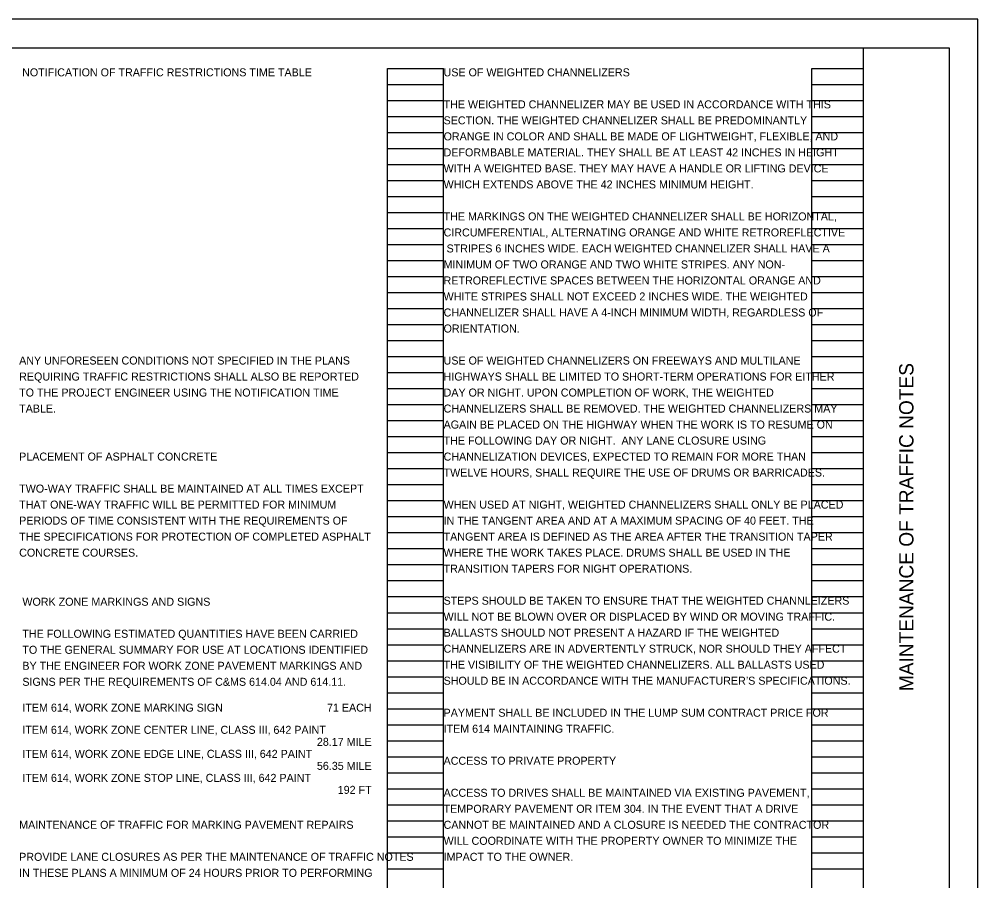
# Model space of a CAD drawing. Extents: x 0 to 34, y -8.1 to 22.
# Drawn here: x 17.24 to 34, y 6.93 to 22 of the extents above; entities that cross this region are included whole.
import ezdxf

# ---------------------------------------------------------------- set-up
doc = ezdxf.new("R2010")
doc.units = 0
for name, color, linetype in [('SH_Border', 7, 'Continuous'), ('SH_Cut_Line', 7, 'Continuous'), ('SH_Data', 7, 'Continuous'), ('SH_Text', 7, 'Continuous')]:
    doc.layers.add(name, color=color, linetype=linetype)

msp = doc.modelspace()

# ---------------------------------------------------------------- linework, layer by layer
at = {"layer": 'SH_Border'}
msp.add_line((32, 0.5), (32, 21.5), dxfattribs=at)
msp.add_lwpolyline([(1.5, 21.5), (33.5, 21.5), (33.5, 0.5), (1.5, 0.5)], close=True, dxfattribs=at)
at = {"layer": 'SH_Cut_Line'}
msp.add_lwpolyline([(0, 0), (34, 0), (34, 22), (0, 22)], close=True, dxfattribs=at)
at = {"layer": 'SH_Data'}
for p, q in [((23.68, 0.98), (23.68, 21.14)), ((23.68, 21.14), (24.66, 21.14)), ((24.66, 0.98), (24.66, 21.14)), ((31.1, 0.98), (31.1, 21.14)), ((31.1, 21.14), (32, 21.14)), ((32, 0.98), (32, 21.14)), ((23.68, 20.86), (24.66, 20.86)), ((31.1, 20.86), (32, 20.86)), ((23.68, 20.58), (24.66, 20.58)), ((31.1, 20.58), (32, 20.58)), ((23.68, 20.3), (24.66, 20.3)), ((31.1, 20.3), (32, 20.3)), ((23.68, 20.02), (24.66, 20.02)), ((31.1, 20.02), (32, 20.02)), ((23.68, 19.74), (24.66, 19.74)), ((31.1, 19.74), (32, 19.74)), ((23.68, 19.46), (24.66, 19.46)), ((31.1, 19.46), (32, 19.46)), ((23.68, 19.18), (24.66, 19.18)), ((31.1, 19.18), (32, 19.18)), ((23.68, 18.9), (24.66, 18.9)), ((31.1, 18.9), (32, 18.9)), ((23.68, 18.62), (24.66, 18.62)), ((31.1, 18.62), (32, 18.62)), ((23.68, 18.34), (24.66, 18.34)), ((31.1, 18.34), (32, 18.34)), ((23.68, 18.06), (24.66, 18.06)), ((31.1, 18.06), (32, 18.06)), ((23.68, 17.78), (24.66, 17.78)), ((31.1, 17.78), (32, 17.78)), ((23.68, 17.5), (24.66, 17.5)), ((31.1, 17.5), (32, 17.5)), ((23.68, 17.22), (24.66, 17.22)), ((31.1, 17.22), (32, 17.22)), ((23.68, 16.94), (24.66, 16.94)), ((31.1, 16.94), (32, 16.94)), ((23.68, 16.66), (24.66, 16.66)), ((31.1, 16.66), (32, 16.66)), ((23.68, 16.38), (24.66, 16.38)), ((31.1, 16.38), (32, 16.38)), ((23.68, 16.1), (24.66, 16.1)), ((31.1, 16.1), (32, 16.1)), ((23.68, 15.82), (24.66, 15.82)), ((31.1, 15.82), (32, 15.82)), ((23.68, 15.54), (24.66, 15.54)), ((31.1, 15.54), (32, 15.54)), ((23.68, 15.26), (24.66, 15.26)), ((31.1, 15.26), (32, 15.26)), ((23.68, 14.98), (24.66, 14.98)), ((31.1, 14.98), (32, 14.98)), ((23.68, 14.7), (24.66, 14.7)), ((31.1, 14.7), (32, 14.7)), ((23.68, 14.42), (24.66, 14.42)), ((31.1, 14.42), (32, 14.42)), ((23.68, 14.14), (24.66, 14.14)), ((31.1, 14.14), (32, 14.14)), ((23.68, 13.86), (24.66, 13.86)), ((31.1, 13.86), (32, 13.86)), ((23.68, 13.58), (24.66, 13.58)), ((31.1, 13.58), (32, 13.58)), ((23.68, 13.3), (24.66, 13.3)), ((31.1, 13.3), (32, 13.3)), ((23.68, 13.02), (24.66, 13.02)), ((31.1, 13.02), (32, 13.02)), ((23.68, 12.74), (24.66, 12.74)), ((31.1, 12.74), (32, 12.74)), ((23.68, 12.46), (24.66, 12.46)), ((31.1, 12.46), (32, 12.46)), ((23.68, 12.18), (24.66, 12.18)), ((31.1, 12.18), (32, 12.18)), ((23.68, 11.9), (24.66, 11.9)), ((31.1, 11.9), (32, 11.9)), ((23.68, 11.62), (24.66, 11.62)), ((31.1, 11.62), (32, 11.62)), ((23.68, 11.34), (24.66, 11.34)), ((31.1, 11.34), (32, 11.34)), ((23.68, 11.06), (24.66, 11.06)), ((31.1, 11.06), (32, 11.06)), ((23.68, 10.78), (24.66, 10.78)), ((31.1, 10.78), (32, 10.78)), ((23.68, 10.5), (24.66, 10.5)), ((31.1, 10.5), (32, 10.5)), ((23.68, 10.22), (24.66, 10.22)), ((31.1, 10.22), (32, 10.22)), ((23.68, 9.94), (24.66, 9.94)), ((31.1, 9.94), (32, 9.94)), ((23.68, 9.66), (24.66, 9.66)), ((31.1, 9.66), (32, 9.66)), ((23.68, 9.38), (24.66, 9.38)), ((31.1, 9.38), (32, 9.38)), ((23.68, 9.1), (24.66, 9.1)), ((31.1, 9.1), (32, 9.1)), ((23.68, 8.82), (24.66, 8.82)), ((31.1, 8.82), (32, 8.82)), ((23.68, 8.54), (24.66, 8.54)), ((31.1, 8.54), (32, 8.54)), ((23.68, 8.26), (24.66, 8.26)), ((31.1, 8.26), (32, 8.26)), ((23.68, 7.98), (24.66, 7.98)), ((31.1, 7.98), (32, 7.98)), ((23.68, 7.7), (24.66, 7.7)), ((31.1, 7.7), (32, 7.7)), ((23.68, 7.42), (24.66, 7.42)), ((31.1, 7.42), (32, 7.42)), ((23.68, 7.14), (24.66, 7.14)), ((31.1, 7.14), (32, 7.14))]:
    msp.add_line(p, q, dxfattribs=at)

# ---------------------------------------------------------------- texts
msp.add_text('MAINTENANCE OF TRAFFIC NOTES', height=0.25, rotation=90, dxfattribs=at).set_placement((32.875, 10.247))
at = {"layer": 'SH_Text'}
for s, p in [(' NOTIFICATION OF TRAFFIC RESTRICTIONS TIME TABLE', (17.24, 21)), ('USE OF WEIGHTED CHANNELIZERS', (24.66, 21)), ('THE WEIGHTED CHANNELIZER MAY BE USED IN ACCORDANCE WITH THIS ', (24.66, 20.44)), ('SECTION. THE WEIGHTED CHANNELIZER SHALL BE PREDOMINANTLY ', (24.66, 20.16)), ('ORANGE IN COLOR AND SHALL BE MADE OF LIGHTWEIGHT, FLEXIBLE, AND', (24.66, 19.88)), ('DEFORMBABLE MATERIAL. THEY SHALL BE AT LEAST 42 INCHES IN HEIGHT ', (24.66, 19.6)), ('WITH A WEIGHTED BASE. THEY MAY HAVE A HANDLE OR LIFTING DEVICE ', (24.66, 19.32)), ('WHICH EXTENDS ABOVE THE 42 INCHES MINIMUM HEIGHT.', (24.66, 19.04)), ('THE MARKINGS ON THE WEIGHTED CHANNELIZER SHALL BE HORIZONTAL, ', (24.66, 18.48)), ('CIRCUMFERENTIAL, ALTERNATING ORANGE AND WHITE RETROREFLECTIVE', (24.66, 18.2)), (' STRIPES 6 INCHES WIDE. EACH WEIGHTED CHANNELIZER SHALL HAVE A ', (24.66, 17.92)), ('MINIMUM OF TWO ORANGE AND TWO WHITE STRIPES. ANY NON-', (24.66, 17.64)), ('RETROREFLECTIVE SPACES BETWEEN THE HORIZONTAL ORANGE AND ', (24.66, 17.36)), ('WHITE STRIPES SHALL NOT EXCEED 2 INCHES WIDE. THE WEIGHTED ', (24.66, 17.08)), ('CHANNELIZER SHALL HAVE A 4-INCH MINIMUM WIDTH, REGARDLESS OF ', (24.66, 16.8)), ('ORIENTATION.', (24.66, 16.52)), ('ANY UNFORESEEN CONDITIONS NOT SPECIFIED IN THE PLANS', (17.24, 15.96)), ('USE OF WEIGHTED CHANNELIZERS ON FREEWAYS AND MULTILANE ', (24.66, 15.96)), ('REQUIRING TRAFFIC RESTRICTIONS SHALL ALSO BE REPORTED', (17.24, 15.68)), ('HIGHWAYS SHALL BE LIMITED TO SHORT-TERM OPERATIONS FOR EITHER ', (24.66, 15.68)), ('TO THE PROJECT ENGINEER USING THE NOTIFICATION TIME', (17.24, 15.4)), ('DAY OR NIGHT. UPON COMPLETION OF WORK, THE WEIGHTED ', (24.66, 15.4)), ('TABLE.', (17.24, 15.12)), ('CHANNELIZERS SHALL BE REMOVED. THE WEIGHTED CHANNELIZERS MAY ', (24.66, 15.12)), ('AGAIN BE PLACED ON THE HIGHWAY WHEN THE WORK IS TO RESUME ON ', (24.66, 14.84)), ('THE FOLLOWING DAY OR NIGHT.  ANY LANE CLOSURE USING ', (24.66, 14.56)), ('PLACEMENT OF ASPHALT CONCRETE', (17.24, 14.28)), ('CHANNELIZATION DEVICES, EXPECTED TO REMAIN FOR MORE THAN ', (24.66, 14.28)), ('TWELVE HOURS, SHALL REQUIRE THE USE OF DRUMS OR BARRICADES.', (24.66, 14)), ('TWO-WAY TRAFFIC SHALL BE MAINTAINED AT ALL TIMES EXCEPT', (17.24, 13.72)), ('THAT ONE-WAY TRAFFIC WILL BE PERMITTED FOR MINIMUM', (17.24, 13.44)), ('WHEN USED AT NIGHT, WEIGHTED CHANNELIZERS SHALL ONLY BE PLACED', (24.66, 13.44)), ('PERIODS OF TIME CONSISTENT WITH THE REQUIREMENTS OF', (17.24, 13.16)), ('IN THE TANGENT AREA AND AT A MAXIMUM SPACING OF 40 FEET. THE ', (24.66, 13.16)), ('THE SPECIFICATIONS FOR PROTECTION OF COMPLETED ASPHALT', (17.24, 12.88)), ('TANGENT AREA IS DEFINED AS THE AREA AFTER THE TRANSITION TAPER ', (24.66, 12.88)), ('CONCRETE COURSES.', (17.24, 12.6)), ('WHERE THE WORK TAKES PLACE. DRUMS SHALL BE USED IN THE ', (24.66, 12.6)), ('TRANSITION TAPERS FOR NIGHT OPERATIONS. ', (24.66, 12.32)), ('STEPS SHOULD BE TAKEN TO ENSURE THAT THE WEIGHTED CHANNLEIZERS ', (24.66, 11.76)), ('WORK ZONE MARKINGS AND SIGNS', (17.296, 11.741)), ('WILL NOT BE BLOWN OVER OR DISPLACED BY WIND OR MOVING TRAFFIC. ', (24.66, 11.48)), ('THE FOLLOWING ESTIMATED QUANTITIES HAVE BEEN CARRIED', (17.296, 11.181)), ('BALLASTS SHOULD NOT PRESENT A HAZARD IF THE WEIGHTED ', (24.66, 11.2)), ('CHANNELIZERS ARE IN ADVERTENTLY STRUCK, NOR SHOULD THEY AFFECT ', (24.66, 10.92)), ('TO THE GENERAL SUMMARY FOR USE AT LOCATIONS IDENTIFIED', (17.296, 10.901)), ('BY THE ENGINEER FOR WORK ZONE PAVEMENT MARKINGS AND', (17.296, 10.621)), ('THE VISIBILITY OF THE WEIGHTED CHANNELIZERS. ALL BALLASTS USED ', (24.66, 10.64)), ('SIGNS PER THE REQUIREMENTS OF C&MS 614.04 AND 614.11.', (17.296, 10.341)), ('SHOULD BE IN ACCORDANCE WITH THE MANUFACTURER’S SPECIFICATIONS.', (24.66, 10.36)), ('ITEM 614, WORK ZONE MARKING SIGN                                   71 EACH', (17.296, 9.889)), ('PAYMENT SHALL BE INCLUDED IN THE LUMP SUM CONTRACT PRICE FOR ', (24.66, 9.8)), ('ITEM 614, WORK ZONE CENTER LINE, CLASS III, 642 PAINT', (17.296, 9.501)), ('ITEM 614 MAINTAINING TRAFFIC.', (24.66, 9.52)), ('                                                                                                   28.17 MILE', (17.296, 9.291)), ('ITEM 614, WORK ZONE EDGE LINE, CLASS III, 642 PAINT', (17.296, 9.081)), ('ACCESS TO PRIVATE PROPERTY', (24.66, 8.96)), ('                                                                                                   56.35 MILE', (17.296, 8.871)), ('ITEM 614, WORK ZONE STOP LINE, CLASS III, 642 PAINT', (17.296, 8.661)), ('                                                                                                          192 FT                                                 ', (17.296, 8.451)), ('ACCESS TO DRIVES SHALL BE MAINTAINED VIA EXISTING PAVEMENT, ', (24.66, 8.4)), ('TEMPORARY PAVEMENT OR ITEM 304. IN THE EVENT THAT A DRIVE ', (24.66, 8.12)), ('MAINTENANCE OF TRAFFIC FOR MARKING PAVEMENT REPAIRS', (17.24, 7.84)), ('CANNOT BE MAINTAINED AND A CLOSURE IS NEEDED THE CONTRACTOR ', (24.66, 7.84)), ('WILL COORDINATE WITH THE PROPERTY OWNER TO MINIMIZE THE ', (24.66, 7.56)), ('PROVIDE LANE CLOSURES AS PER THE MAINTENANCE OF TRAFFIC NOTES ', (17.24, 7.28)), ('IMPACT TO THE OWNER.', (24.66, 7.28)), ('IN THESE PLANS A MINIMUM OF 24 HOURS PRIOR TO PERFORMING ', (17.24, 7))]:
    msp.add_text(s, height=0.14, dxfattribs=at).set_placement(p)

doc.saveas('drawing.dxf')
